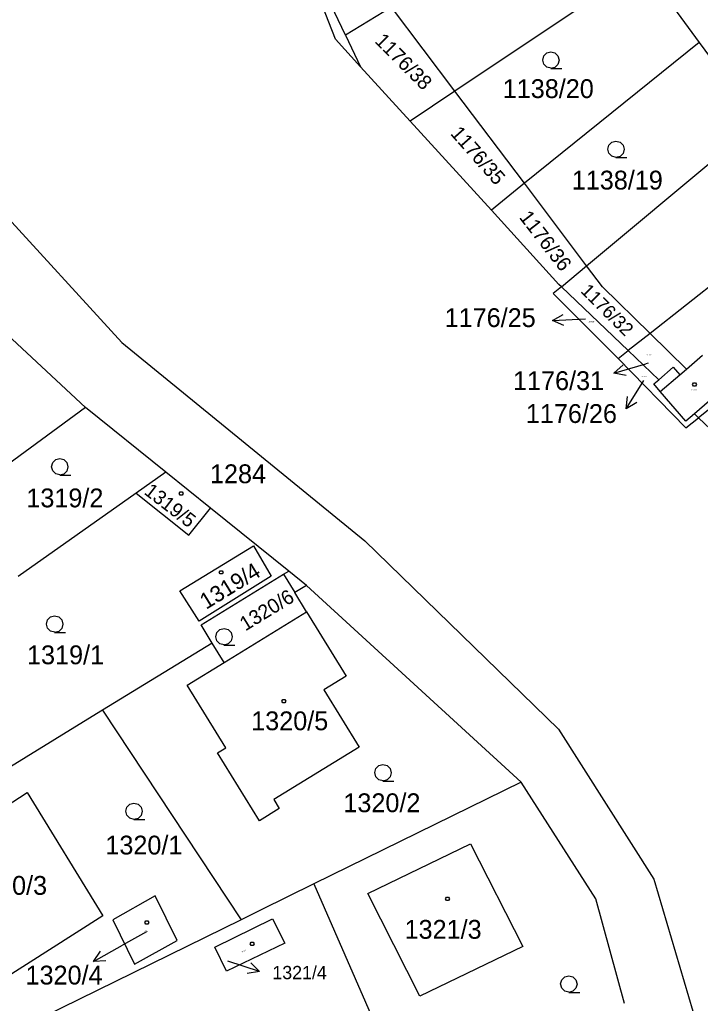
# Model space of a CAD drawing. Extents: x -621797 to -620972, y -1175539 to -1174697.
# Drawn here: x -621498.7 to -621437.2, y -1175451.4 to -1175362.6 of the extents above; entities that cross this region are included whole.
import ezdxf

# ---------------------------------------------------------------- set-up
doc = ezdxf.new("R2010")
doc.units = 0
for name, color, linetype in [('INZ mimo EON - nadz', 7, 'Continuous'), ('Rozvod plynu EON', 7, 'Continuous'), ('SDEL EON', 7, 'Continuous'), ('SDEL EON - popis', 7, 'Continuous'), ('Silnoproud EON', 7, 'Continuous'), ('Silnoproud EON - popis', 7, 'Continuous')]:
    doc.layers.add(name, color=color, linetype=linetype)

msp = doc.modelspace()

# ---------------------------------------------------------------- linework, layer by layer
at = {"layer": 'INZ mimo EON - nadz'}
for p, q in [((-621450.596, -1175389.767), (-621447.6, -1175389.61)), ((-621445.044, -1175394.507), (-621442.16, -1175393.68)), ((-621441.94, -1175393.62), (-621442.16, -1175393.68)), ((-621443.93, -1175397.734), (-621442.34, -1175395.19)), ((-621487.23, -1175444.97), (-621489.39, -1175446.18)), ((-621492.008, -1175447.645), (-621489.39, -1175446.18)), ((-621477.027, -1175448.548), (-621479.88, -1175447.62))]:
    msp.add_line(p, q, dxfattribs=at)
for points in [[(-621449.571, -1175390.214), (-621450.596, -1175389.767), (-621449.623, -1175389.215)], [(-621443.945, -1175394.712), (-621445.044, -1175394.507), (-621444.22, -1175393.751)], [(-621442.976, -1175397.151), (-621443.93, -1175397.734), (-621443.824, -1175396.621)], [(-621490.891, -1175447.593), (-621492.008, -1175447.645), (-621491.379, -1175446.72)], [(-621477.823, -1175447.763), (-621477.027, -1175448.548), (-621478.133, -1175448.714)]]:
    msp.add_lwpolyline(points, dxfattribs=at)
at = {"layer": 'Rozvod plynu EON'}
for points in [[(-621437.68, -1175395.4), (-621437.59, -1175395.55), (-621437.68, -1175395.7), (-621437.86, -1175395.7), (-621437.95, -1175395.55), (-621437.86, -1175395.4)], [(-621484.01, -1175405.24), (-621483.92, -1175405.39), (-621484.01, -1175405.54), (-621484.19, -1175405.54), (-621484.28, -1175405.39), (-621484.19, -1175405.24)], [(-621480.39, -1175412.35), (-621480.3, -1175412.5), (-621480.39, -1175412.65), (-621480.57, -1175412.65), (-621480.66, -1175412.5), (-621480.57, -1175412.35)], [(-621474.74, -1175423.97), (-621474.65, -1175424.12), (-621474.74, -1175424.27), (-621474.92, -1175424.27), (-621475.01, -1175424.12), (-621474.92, -1175423.97)], [(-621459.97, -1175441.84), (-621459.88, -1175441.99), (-621459.97, -1175442.14), (-621460.15, -1175442.14), (-621460.24, -1175441.99), (-621460.15, -1175441.84)], [(-621487.11, -1175443.97), (-621487.02, -1175444.12), (-621487.11, -1175444.27), (-621487.29, -1175444.27), (-621487.38, -1175444.12), (-621487.29, -1175443.97)], [(-621477.61, -1175445.91), (-621477.52, -1175446.06), (-621477.61, -1175446.21), (-621477.79, -1175446.21), (-621477.88, -1175446.06), (-621477.79, -1175445.91)]]:
    msp.add_lwpolyline(points, close=True, dxfattribs=at)
at = {"layer": 'SDEL EON'}
for points in [[(-621450.72, -1175366.98), (-621451.1, -1175366.88), (-621451.37, -1175366.61), (-621451.47, -1175366.24), (-621451.37, -1175365.87), (-621451.1, -1175365.6), (-621450.73, -1175365.5), (-621450.36, -1175365.6), (-621450.09, -1175365.87), (-621449.99, -1175366.25), (-621450.09, -1175366.63), (-621450.36, -1175366.9), (-621450.74, -1175367), (-621449.74, -1175367)], [(-621444.85, -1175375.03), (-621445.23, -1175374.93), (-621445.5, -1175374.66), (-621445.6, -1175374.29), (-621445.5, -1175373.92), (-621445.23, -1175373.65), (-621444.86, -1175373.55), (-621444.49, -1175373.65), (-621444.22, -1175373.92), (-621444.12, -1175374.3), (-621444.22, -1175374.68), (-621444.49, -1175374.95), (-621444.87, -1175375.05), (-621443.87, -1175375.05)], [(-621495.04, -1175403.7), (-621495.42, -1175403.6), (-621495.69, -1175403.33), (-621495.79, -1175402.96), (-621495.69, -1175402.59), (-621495.42, -1175402.32), (-621495.05, -1175402.22), (-621494.68, -1175402.32), (-621494.41, -1175402.59), (-621494.31, -1175402.97), (-621494.41, -1175403.35), (-621494.68, -1175403.62), (-621495.06, -1175403.72), (-621494.06, -1175403.72)], [(-621495.51, -1175417.91), (-621495.89, -1175417.81), (-621496.16, -1175417.54), (-621496.26, -1175417.17), (-621496.16, -1175416.8), (-621495.89, -1175416.53), (-621495.52, -1175416.43), (-621495.15, -1175416.53), (-621494.88, -1175416.8), (-621494.78, -1175417.18), (-621494.88, -1175417.56), (-621495.15, -1175417.83), (-621495.53, -1175417.93), (-621494.53, -1175417.93)], [(-621480.22, -1175419.05), (-621480.6, -1175418.95), (-621480.87, -1175418.68), (-621480.97, -1175418.31), (-621480.87, -1175417.94), (-621480.6, -1175417.67), (-621480.23, -1175417.57), (-621479.86, -1175417.67), (-621479.59, -1175417.94), (-621479.49, -1175418.32), (-621479.59, -1175418.7), (-621479.86, -1175418.97), (-621480.24, -1175419.07), (-621479.24, -1175419.07)], [(-621465.88, -1175431.33), (-621466.26, -1175431.23), (-621466.53, -1175430.96), (-621466.63, -1175430.59), (-621466.53, -1175430.22), (-621466.26, -1175429.95), (-621465.89, -1175429.85), (-621465.52, -1175429.95), (-621465.25, -1175430.22), (-621465.15, -1175430.6), (-621465.25, -1175430.98), (-621465.52, -1175431.25), (-621465.9, -1175431.35), (-621464.9, -1175431.35)], [(-621488.35, -1175434.81), (-621488.73, -1175434.71), (-621489, -1175434.44), (-621489.1, -1175434.07), (-621489, -1175433.7), (-621488.73, -1175433.43), (-621488.36, -1175433.33), (-621487.99, -1175433.43), (-621487.72, -1175433.7), (-621487.62, -1175434.08), (-621487.72, -1175434.46), (-621487.99, -1175434.73), (-621488.37, -1175434.83), (-621487.37, -1175434.83)], [(-621449.1, -1175450.41), (-621449.48, -1175450.31), (-621449.75, -1175450.04), (-621449.85, -1175449.67), (-621449.75, -1175449.3), (-621449.48, -1175449.03), (-621449.11, -1175448.93), (-621448.74, -1175449.03), (-621448.47, -1175449.3), (-621448.37, -1175449.68), (-621448.47, -1175450.06), (-621448.74, -1175450.33), (-621449.12, -1175450.43), (-621448.12, -1175450.43)]]:
    msp.add_lwpolyline(points, dxfattribs=at)
at = {"layer": 'SDEL EON - popis'}
for p, q in [((-621440.86, -1175396.18), (-621439.09, -1175394.67)), ((-621474.87, -1175412.67), (-621473.85, -1175414.33))]:
    msp.add_line(p, q, dxfattribs=at)
at = {"layer": 'Silnoproud EON'}
for p, q in [((-621470.18, -1175364.36), (-621477.25, -1175346.15)), ((-621469.28, -1175363.99), (-621473.36, -1175355.35)), ((-621442.44, -1175357.7), (-621459.4, -1175369.04)), ((-621442.44, -1175357.7), (-621437.35, -1175364.64)), ((-621465.1, -1175361.47), (-621469.28, -1175363.99)), ((-621459.4, -1175369.04), (-621465.1, -1175361.47)), ((-621469.28, -1175363.99), (-621467.92, -1175366.84)), ((-621467.92, -1175366.84), (-621470.18, -1175364.36)), ((-621437.35, -1175364.64), (-621453.11, -1175377.37)), ((-621437.35, -1175364.64), (-621432.04, -1175371.88)), ((-621512.96, -1175366.06), (-621489.46, -1175391.75)), ((-621463.44, -1175371.75), (-621467.92, -1175366.84)), ((-621459.4, -1175369.04), (-621463.44, -1175371.75)), ((-621453.11, -1175377.37), (-621459.4, -1175369.04)), ((-621456.1, -1175379.79), (-621463.44, -1175371.75)), ((-621447.51, -1175384.81), (-621432.04, -1175371.88)), ((-621453.11, -1175377.37), (-621456.1, -1175379.79)), ((-621447.51, -1175384.81), (-621453.11, -1175377.37)), ((-621426.75, -1175379.09), (-621441.77, -1175390.92)), ((-621450, -1175386.5), (-621456.1, -1175379.79)), ((-621492.72, -1175397.61), (-621511.03, -1175380.61)), ((-621449.78, -1175386.71), (-621447.51, -1175384.81)), ((-621446.07, -1175386.72), (-621447.51, -1175384.81)), ((-621449.78, -1175386.71), (-621450.52, -1175387.32)), ((-621449.78, -1175386.71), (-621450, -1175386.5)), ((-621443.75, -1175392.48), (-621449.78, -1175386.71)), ((-621441.77, -1175390.92), (-621446.07, -1175386.72)), ((-621450.52, -1175387.32), (-621444.65, -1175393.19)), ((-621441.77, -1175390.92), (-621443.75, -1175392.48)), ((-621438.48, -1175394.14), (-621441.77, -1175390.92)), ((-621489.46, -1175391.75), (-621467.52, -1175409.66)), ((-621444.65, -1175393.19), (-621443.75, -1175392.48)), ((-621441, -1175395.11), (-621443.75, -1175392.48)), ((-621444.65, -1175393.19), (-621438.56, -1175399.45)), ((-621438.48, -1175394.14), (-621437.05, -1175392.89)), ((-621441, -1175395.11), (-621439.7, -1175393.98)), ((-621439.7, -1175393.98), (-621439.09, -1175394.67)), ((-621439.09, -1175394.67), (-621438.48, -1175394.14)), ((-621441.44, -1175395.49), (-621441, -1175395.11)), ((-621440.86, -1175396.18), (-621441.44, -1175395.49)), ((-621438.55, -1175398.85), (-621440.86, -1175396.18)), ((-621435.95, -1175396.62), (-621437.78, -1175398.19)), ((-621492.72, -1175397.61), (-621504.77, -1175406.46)), ((-621485.48, -1175403.44), (-621492.72, -1175397.61)), ((-621435.51, -1175397.05), (-621437.41, -1175398.54)), ((-621438.56, -1175399.45), (-621437.41, -1175398.54)), ((-621437.78, -1175398.19), (-621438.55, -1175398.85)), ((-621437.41, -1175398.54), (-621437.78, -1175398.19)), ((-621431.67, -1175404.03), (-621437.41, -1175398.54)), ((-621485.48, -1175403.44), (-621488.16, -1175405.34)), ((-621481.45, -1175406.69), (-621485.48, -1175403.44)), ((-621488.16, -1175405.34), (-621498.81, -1175412.88)), ((-621488.16, -1175405.34), (-621483.41, -1175409.15)), ((-621483.41, -1175409.15), (-621481.45, -1175406.69)), ((-621474.39, -1175412.38), (-621481.45, -1175406.69)), ((-621484.22, -1175414.17), (-621477.58, -1175410.12)), ((-621477.58, -1175410.12), (-621475.96, -1175412.86)), ((-621467.52, -1175409.66), (-621450.05, -1175426.66)), ((-621475.96, -1175412.86), (-621482.48, -1175416.9)), ((-621482.3, -1175417.24), (-621474.87, -1175412.67)), ((-621474.87, -1175412.67), (-621474.39, -1175412.38)), ((-621472.78, -1175413.68), (-621474.39, -1175412.38)), ((-621472.78, -1175413.68), (-621473.85, -1175414.33)), ((-621453.41, -1175431.45), (-621472.78, -1175413.68)), ((-621482.48, -1175416.9), (-621484.22, -1175414.17)), ((-621472.78, -1175416.07), (-621473.85, -1175414.33)), ((-621480.21, -1175420.63), (-621472.78, -1175416.07)), ((-621472.78, -1175416.07), (-621469.21, -1175421.88)), ((-621481.29, -1175418.89), (-621482.3, -1175417.24)), ((-621481.29, -1175418.89), (-621491.19, -1175424.96)), ((-621480.21, -1175420.63), (-621481.29, -1175418.89)), ((-621483.56, -1175422.69), (-621480.21, -1175420.63)), ((-621480.08, -1175428.36), (-621483.56, -1175422.69)), ((-621469.21, -1175421.88), (-621471.21, -1175423.11)), ((-621471.21, -1175423.11), (-621468.03, -1175428.28)), ((-621491.19, -1175424.96), (-621492.9, -1175426.01)), ((-621491.19, -1175424.96), (-621478.69, -1175443.87)), ((-621492.9, -1175426.01), (-621512.82, -1175438.21)), ((-621450.05, -1175426.66), (-621441.44, -1175440.21)), ((-621480.81, -1175428.8), (-621480.08, -1175428.36)), ((-621477.04, -1175434.94), (-621480.81, -1175428.8)), ((-621468.03, -1175428.28), (-621475.74, -1175433.02)), ((-621453.41, -1175431.45), (-621472.11, -1175440.64)), ((-621446.68, -1175441.99), (-621453.41, -1175431.45)), ((-621506.4, -1175437.81), (-621497.99, -1175432.37)), ((-621497.99, -1175432.37), (-621491.16, -1175443.51)), ((-621475.74, -1175433.02), (-621475.24, -1175433.83)), ((-621475.24, -1175433.83), (-621477.04, -1175434.94)), ((-621467.26, -1175441.5), (-621457.99, -1175437.01)), ((-621457.99, -1175437.01), (-621453.26, -1175446.29)), ((-621441.44, -1175440.21), (-621435.99, -1175458.63)), ((-621472.11, -1175440.64), (-621476.87, -1175442.97)), ((-621472.11, -1175440.64), (-621462.68, -1175462.26)), ((-621486.45, -1175441.72), (-621490.27, -1175443.87)), ((-621484.47, -1175445.76), (-621486.45, -1175441.72)), ((-621462.55, -1175450.78), (-621467.26, -1175441.5)), ((-621444.1, -1175451.45), (-621446.68, -1175441.99)), ((-621476.87, -1175442.97), (-621478.69, -1175443.87)), ((-621478.69, -1175443.87), (-621505.14, -1175456.86)), ((-621491.16, -1175443.51), (-621500.5, -1175449.46)), ((-621490.27, -1175443.87), (-621488.3, -1175447.89)), ((-621481.07, -1175446.35), (-621475.84, -1175443.79)), ((-621475.84, -1175443.79), (-621474.75, -1175445.99)), ((-621488.3, -1175447.89), (-621484.47, -1175445.76)), ((-621480, -1175448.53), (-621481.07, -1175446.35)), ((-621474.75, -1175445.99), (-621480, -1175448.53)), ((-621453.26, -1175446.29), (-621462.55, -1175450.78))]:
    msp.add_line(p, q, dxfattribs=at)

# ---------------------------------------------------------------- texts
at = {"layer": 'INZ mimo EON - nadz'}
for s, height, p in [('1176/25', 1.7, (-621460.317, -1175390.35)), ('1176/31', 1.7, (-621454.147, -1175396.04)), ('1176/26', 1.7, (-621452.987, -1175399.01)), ('1284', 1.7, (-621481.497, -1175404.45)), ('1320/4', 1.7, (-621498.142, -1175449.72)), ('1321/4', 1.2, (-621475.863, -1175449.24))]:
    msp.add_text(s, height=height, dxfattribs=at).set_placement(p)
at = {"layer": 'Silnoproud EON - popis'}
for s, height, rotation, p in [('1176/38', 1.3, 315.01219, (-621466.698, -1175364.602)), ('1176/35', 1.3, 311.40256, (-621459.861, -1175372.915)), ('1176/36', 1.3, 307.79293, (-621453.646, -1175380.457)), ('1176/32', 1.2, 315.01219, (-621448.114, -1175387.166)), ('1319/5', 1.27, 322.40335, (-621487.527, -1175405.367)), ('1319/4', 1.45, 31.62727, (-621481.842, -1175415.891)), ('1320/6', 1.3, 31.51268, (-621478.304, -1175417.843)), ('1321/4', 0.1, 24.29341, (-621478.609, -1175446.83))]:
    msp.add_text(s, height=height, rotation=rotation, dxfattribs=at).set_placement(p)
for s, height, p in [('1138/20', 1.7, (-621455.077, -1175369.67)), ('1138/19', 1.7, (-621448.847, -1175377.93)), ('1176/25', 0.1, (-621447.317, -1175389.91)), ('1176/31', 0.1, (-621442.127, -1175392.91)), ('1176/26', 0.1, (-621442.607, -1175394.87)), ('1176/28', 0.1, (-621438.047, -1175396.07)), ('1319/2', 1.7, (-621498.067, -1175406.63)), ('1319/1', 1.7, (-621498.007, -1175420.8)), ('1320/5', 1.7, (-621477.777, -1175426.76)), ('1320/2', 1.7, (-621469.457, -1175434.16)), ('1320/1', 1.7, (-621490.937, -1175437.98)), ('1320/3', 1.7, (-621503.149, -1175441.62)), ('1321/3', 1.7, (-621463.934, -1175445.59)), ('1320/4', 0.1, (-621487.463, -1175444.97))]:
    msp.add_text(s, height=height, dxfattribs=at).set_placement(p)

doc.saveas('drawing.dxf')
